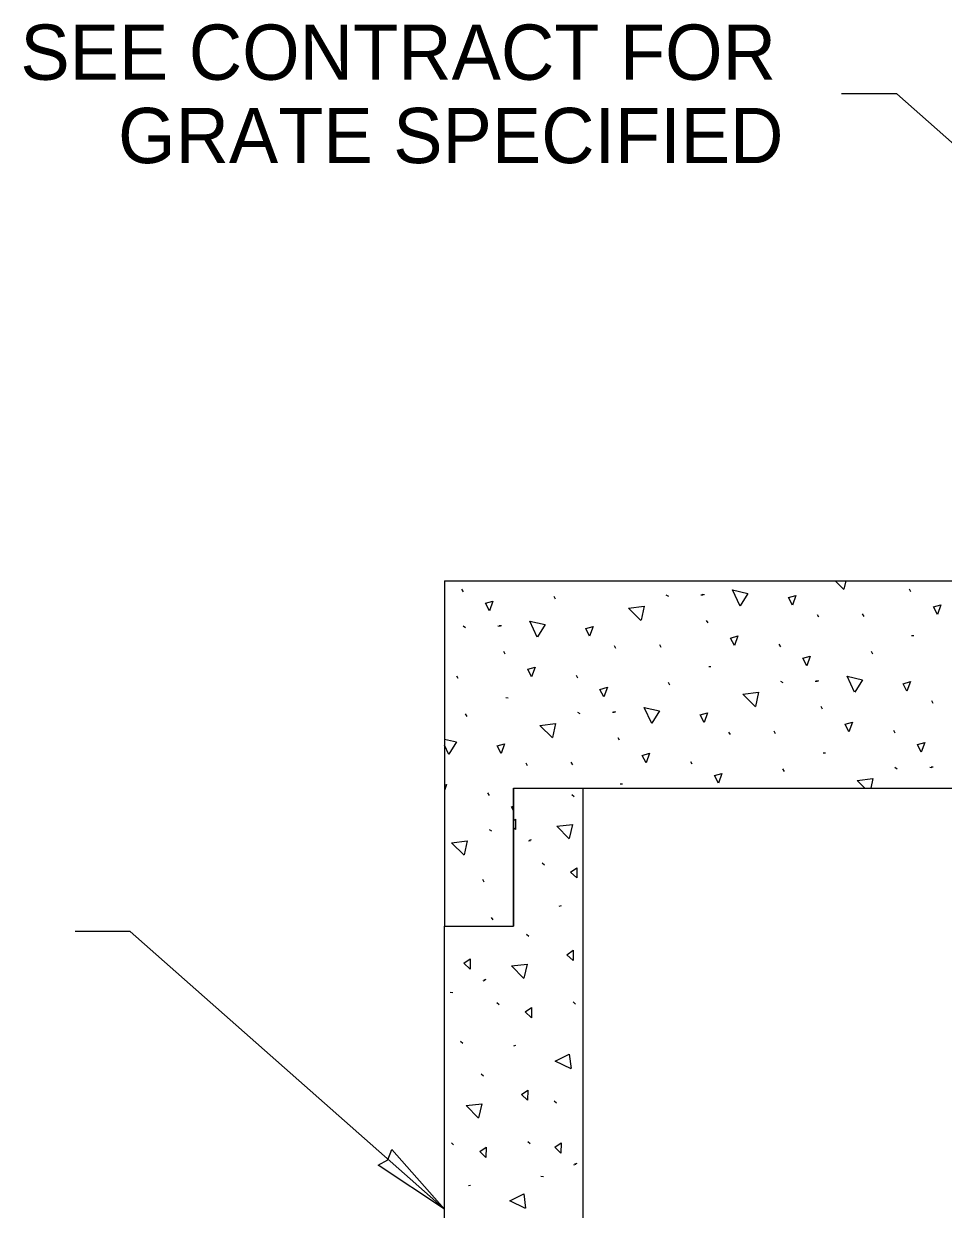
# Model space of a CAD drawing. Extents: x 99862 to 103151, y 100000 to 102076.
# Drawn here: x 100983.3 to 101249.5, y 100451.4 to 100794.6 of the extents above; entities that cross this region are included whole.
import ezdxf

# ---------------------------------------------------------------- set-up
doc = ezdxf.new("R2010")
doc.units = 0
for name, color, linetype in [('Level 15', 7, 'Continuous'), ('Level 20', 7, 'Continuous'), ('Level 27', 7, 'Continuous'), ('Level 5', 7, 'Continuous'), ('Level 7', 7, 'Continuous')]:
    doc.layers.add(name, color=color, linetype=linetype)

msp = doc.modelspace()

# ---------------------------------------------------------------- linework, layer by layer
at = {"layer": 'Level 15'}
for points in [[(101326.96, 100693.97), (101236.03, 100774.32), (101220.03, 100774.32)], [(101105.1, 100451.44), (101014.16, 100531.8), (100998.16, 100531.8)]]:
    msp.add_lwpolyline(points, dxfattribs=at)
msp.add_lwpolyline([(101105.1, 100451.44), (101085.9, 100464.15), (101088.65, 100465.71), (101089.81, 100468.66)], close=True, dxfattribs=at)
at = {"layer": 'Level 27'}
msp.add_line((101142.63, 100570.81), (101141.98, 100571.39), dxfattribs=at)
at = {"layer": 'Level 5'}
for p, q in [((101105.1, 100633.34), (101105.1, 100533.34)), ((101105.1, 100633.34), (101284.28, 100633.34)), ((101110.56, 100630.15), (101110.14, 100630.91)), ((101137.24, 100628.05), (101136.82, 100628.82)), ((101169.21, 100629.29), (101169.9, 100628.88)), ((101179.3, 100629.27), (101179.94, 100629.24)), ((101179.68, 100629.44), (101180.32, 100629.4)), ((101240.13, 100630.14), (101239.71, 100630.9)), ((101181.4, 100621.13), (101180.98, 100621.89)), ((101213.45, 100622.78), (101213.02, 100623.54)), ((101226.54, 100623.03), (101226.11, 100623.8)), ((101110.48, 100620.28), (101111.17, 100619.87)), ((101120.57, 100620.27), (101121.21, 100620.23)), ((101120.95, 100620.43), (101121.59, 100620.39)), ((101167.81, 100614.03), (101167.39, 100614.79)), ((101202.42, 100614.19), (101201.99, 100614.96)), ((101240.32, 100617.54), (101240.96, 100617.51)), ((101122.68, 100612.12), (101122.25, 100612.88)), ((101154.72, 100613.77), (101154.3, 100614.54)), ((101229.1, 100612.1), (101228.67, 100612.86)), ((101181.59, 100608.54), (101182.23, 100608.5)), ((101109.08, 100605.02), (101108.66, 100605.78)), ((101143.69, 100605.18), (101143.26, 100605.95)), ((101202.34, 100604.33), (101203.03, 100603.92)), ((101212.43, 100604.31), (101213.07, 100604.27)), ((101212.8, 100604.47), (101213.44, 100604.43)), ((101170.37, 100603.09), (101169.94, 100603.86)), ((101122.86, 100599.53), (101123.5, 100599.49)), ((101246.58, 100597.81), (101246.15, 100598.58)), ((101111.64, 100594.08), (101111.22, 100594.85)), ((101143.61, 100595.32), (101144.3, 100594.91)), ((101153.7, 100595.3), (101154.34, 100595.27)), ((101154.08, 100595.46), (101154.72, 100595.43)), ((101214.53, 100596.16), (101214.11, 100596.93)), ((101155.8, 100587.16), (101155.38, 100587.92)), ((101187.85, 100588.81), (101187.42, 100589.57)), ((101200.94, 100589.06), (101200.51, 100589.83)), ((101235.55, 100589.23), (101235.12, 100589.99)), ((101129.12, 100579.8), (101128.7, 100580.56)), ((101142.21, 100580.05), (101141.79, 100580.82)), ((101176.82, 100580.22), (101176.39, 100580.98)), ((101214.72, 100583.57), (101215.36, 100583.53)), ((101203.5, 100578.13), (101203.07, 100578.89)), ((101235.46, 100579.36), (101236.16, 100578.95)), ((101245.56, 100579.35), (101246.2, 100579.31)), ((101245.93, 100579.51), (101246.57, 100579.47)), ((101155.99, 100574.56), (101156.63, 100574.53)), ((101118.09, 100571.21), (101117.66, 100571.98)), ((101125.1, 100573.34), (101125.1, 100533.34)), ((101125.1, 100573.34), (101284.28, 100573.34)), ((101118.01, 100561.35), (101118.7, 100560.94)), ((101116.61, 100546.08), (101116.19, 100546.85)), ((101119.17, 100535.15), (101118.75, 100535.91)), ((101105.1, 100533.34), (101125.1, 100533.34))]:
    msp.add_line(p, q, dxfattribs=at)
for points in [[(101220.68, 100630.85), (101218.19, 100633.34)], [(101221.23, 100633.34), (101220.71, 100630.94)], [(101190.67, 100626.05), (101188.49, 100630.69), (101192.95, 100629.66), (101190.72, 100626.12)], [(101205.83, 100626.32), (101204.7, 100628.51), (101206.83, 100629.12), (101205.83, 100626.32)], [(101118.11, 100624.68), (101116.98, 100626.86), (101119.11, 100627.48), (101118.11, 100624.68)], [(101161.96, 100621.85), (101158.33, 100625.46), (101162.86, 100626.03), (101161.98, 100621.93)], [(101247.77, 100623.6), (101246.64, 100625.79), (101248.77, 100626.4), (101247.77, 100623.6)], [(101131.94, 100617.04), (101129.77, 100621.68), (101134.22, 100620.66), (101131.99, 100617.11)], [(101147.1, 100617.31), (101145.97, 100619.5), (101148.1, 100620.11), (101147.1, 100617.31)], [(101189.04, 100614.59), (101187.91, 100616.78), (101190.04, 100617.4), (101189.04, 100614.59)], [(101209.97, 100608.72), (101208.84, 100610.91), (101210.97, 100611.52), (101209.97, 100608.72)], [(101130.32, 100605.58), (101129.18, 100607.77), (101131.32, 100608.39), (101130.32, 100605.58)], [(101223.8, 100601.08), (101221.62, 100605.72), (101226.08, 100604.7), (101223.85, 100601.15)], [(101151.24, 100599.71), (101150.11, 100601.9), (101152.24, 100602.52), (101151.24, 100599.71)], [(101195.08, 100596.88), (101191.45, 100600.5), (101195.99, 100601.06), (101195.11, 100596.97)], [(101238.96, 100601.35), (101237.83, 100603.54), (101239.96, 100604.16), (101238.96, 100601.35)], [(101165.07, 100592.07), (101162.9, 100596.71), (101167.35, 100595.69), (101165.12, 100592.14)], [(101180.23, 100592.35), (101179.1, 100594.53), (101181.23, 100595.15), (101180.23, 100592.35)], [(101136.36, 100587.87), (101132.73, 100591.49), (101137.26, 100592.05), (101136.38, 100587.96)], [(101222.17, 100589.63), (101221.04, 100591.82), (101223.17, 100592.43), (101222.17, 100589.63)], [(101105.1, 100587.49), (101108.62, 100586.68), (101106.39, 100583.14)], [(101106.34, 100583.07), (101105.1, 100585.72)], [(101121.5, 100583.34), (101120.37, 100585.53), (101122.5, 100586.14), (101121.5, 100583.34)], [(101243.1, 100583.76), (101241.97, 100585.94), (101244.1, 100586.56), (101243.1, 100583.76)], [(101163.44, 100580.62), (101162.31, 100582.81), (101164.44, 100583.42), (101163.44, 100580.62)], [(101184.37, 100574.75), (101183.24, 100576.94), (101185.37, 100577.55), (101184.37, 100574.75)], [(101105.1, 100574.24), (101105.72, 100574.42), (101105.1, 100572.68)], [(101226.78, 100573.34), (101224.58, 100575.53), (101229.12, 100576.1), (101228.53, 100573.34)], [(101125.1, 100566.8), (101124.51, 100567.93), (101125.1, 100568.1)], [(101110.76, 100553.9), (101107.13, 100557.52), (101111.66, 100558.08), (101110.78, 100553.99)]]:
    msp.add_lwpolyline(points, dxfattribs=at)
at = {"layer": 'Level 7'}
for p, q in [((101125.1, 100533.34), (101125.1, 100573.34)), ((101125.1, 100573.34), (101145.1, 100573.34)), ((101145.1, 100573.34), (101145.1, 100273.34)), ((101129.4, 100558.02), (101130.02, 100558.19)), ((101129.7, 100558.29), (101130.32, 100558.46)), ((101134.04, 100551), (101133.39, 100551.58)), ((101138.32, 100539.15), (101138.93, 100539.32)), ((101105.1, 100273.34), (101105.1, 100533.34)), ((101105.1, 100533.34), (101125.1, 100533.34)), ((101129.48, 100530.35), (101128.83, 100530.94)), ((101116.26, 100517.56), (101116.87, 100517.73)), ((101116.56, 100517.84), (101117.17, 100518.01)), ((101106.71, 100514.29), (101107.49, 100514.13)), ((101120.9, 100510.54), (101120.25, 100511.13)), ((101143.02, 100510.82), (101142.37, 100511.41)), ((101110.36, 100499.4), (101109.71, 100499.99)), ((101125.17, 100498.7), (101125.79, 100498.87)), ((101116.34, 100489.9), (101115.69, 100490.48)), ((101137.51, 100482.08), (101136.86, 100482.67)), ((101107.75, 100470.09), (101107.1, 100470.67)), ((101129.88, 100470.37), (101129.23, 100470.95)), ((101142.56, 100464.29), (101143.18, 100464.46)), ((101142.86, 100464.56), (101143.48, 100464.73)), ((101133.01, 100461.02), (101133.8, 100460.85)), ((101112.03, 100458.24), (101112.64, 100458.41))]:
    msp.add_line(p, q, dxfattribs=at)
for points in [[(101125.1, 100563.96), (101125.67, 100564.36), (101125.64, 100561.39)], [(101125.64, 100561.39), (101125.1, 100561.9)], [(101141.2, 100558.66), (101137.63, 100562.34), (101142.18, 100562.83), (101141.23, 100558.75)], [(101143.39, 100547.31), (101141.61, 100549.01), (101143.43, 100550.28), (101143.39, 100547.31)], [(101142.3, 100523.4), (101140.52, 100525.1), (101142.33, 100526.38), (101142.3, 100523.4)], [(101112.5, 100520.93), (101110.71, 100522.63), (101112.53, 100523.91), (101112.5, 100520.93)], [(101128.06, 100518.21), (101124.49, 100521.89), (101129.04, 100522.37), (101128.08, 100518.29)], [(101130.25, 100506.85), (101128.47, 100508.55), (101130.28, 100509.83), (101130.25, 100506.85)], [(101141.73, 100492.07), (101137.12, 100494.31), (101141.22, 100496.32), (101141.72, 100492.16)], [(101129.16, 100482.95), (101127.37, 100484.65), (101129.19, 100485.92), (101129.16, 100482.95)], [(101114.91, 100477.75), (101111.35, 100481.43), (101115.89, 100481.92), (101114.94, 100477.84)], [(101138.8, 100467.66), (101137.02, 100469.36), (101138.84, 100470.63), (101138.8, 100467.66)], [(101117.1, 100466.39), (101115.32, 100468.09), (101117.14, 100469.37), (101117.1, 100466.39)], [(101128.58, 100451.62), (101123.97, 100453.85), (101128.08, 100455.86), (101128.58, 100451.7)]]:
    msp.add_lwpolyline(points, dxfattribs=at)

# ---------------------------------------------------------------- texts
at = {"layer": 'Level 20'}
for s, p in [('SEE CONTRACT FOR', (100982.33, 100778.39)), ('GRATE SPECIFIED', (101010.61, 100754.26))]:
    msp.add_text(s, height=16, dxfattribs=at).set_placement(p)

doc.saveas('drawing.dxf')
